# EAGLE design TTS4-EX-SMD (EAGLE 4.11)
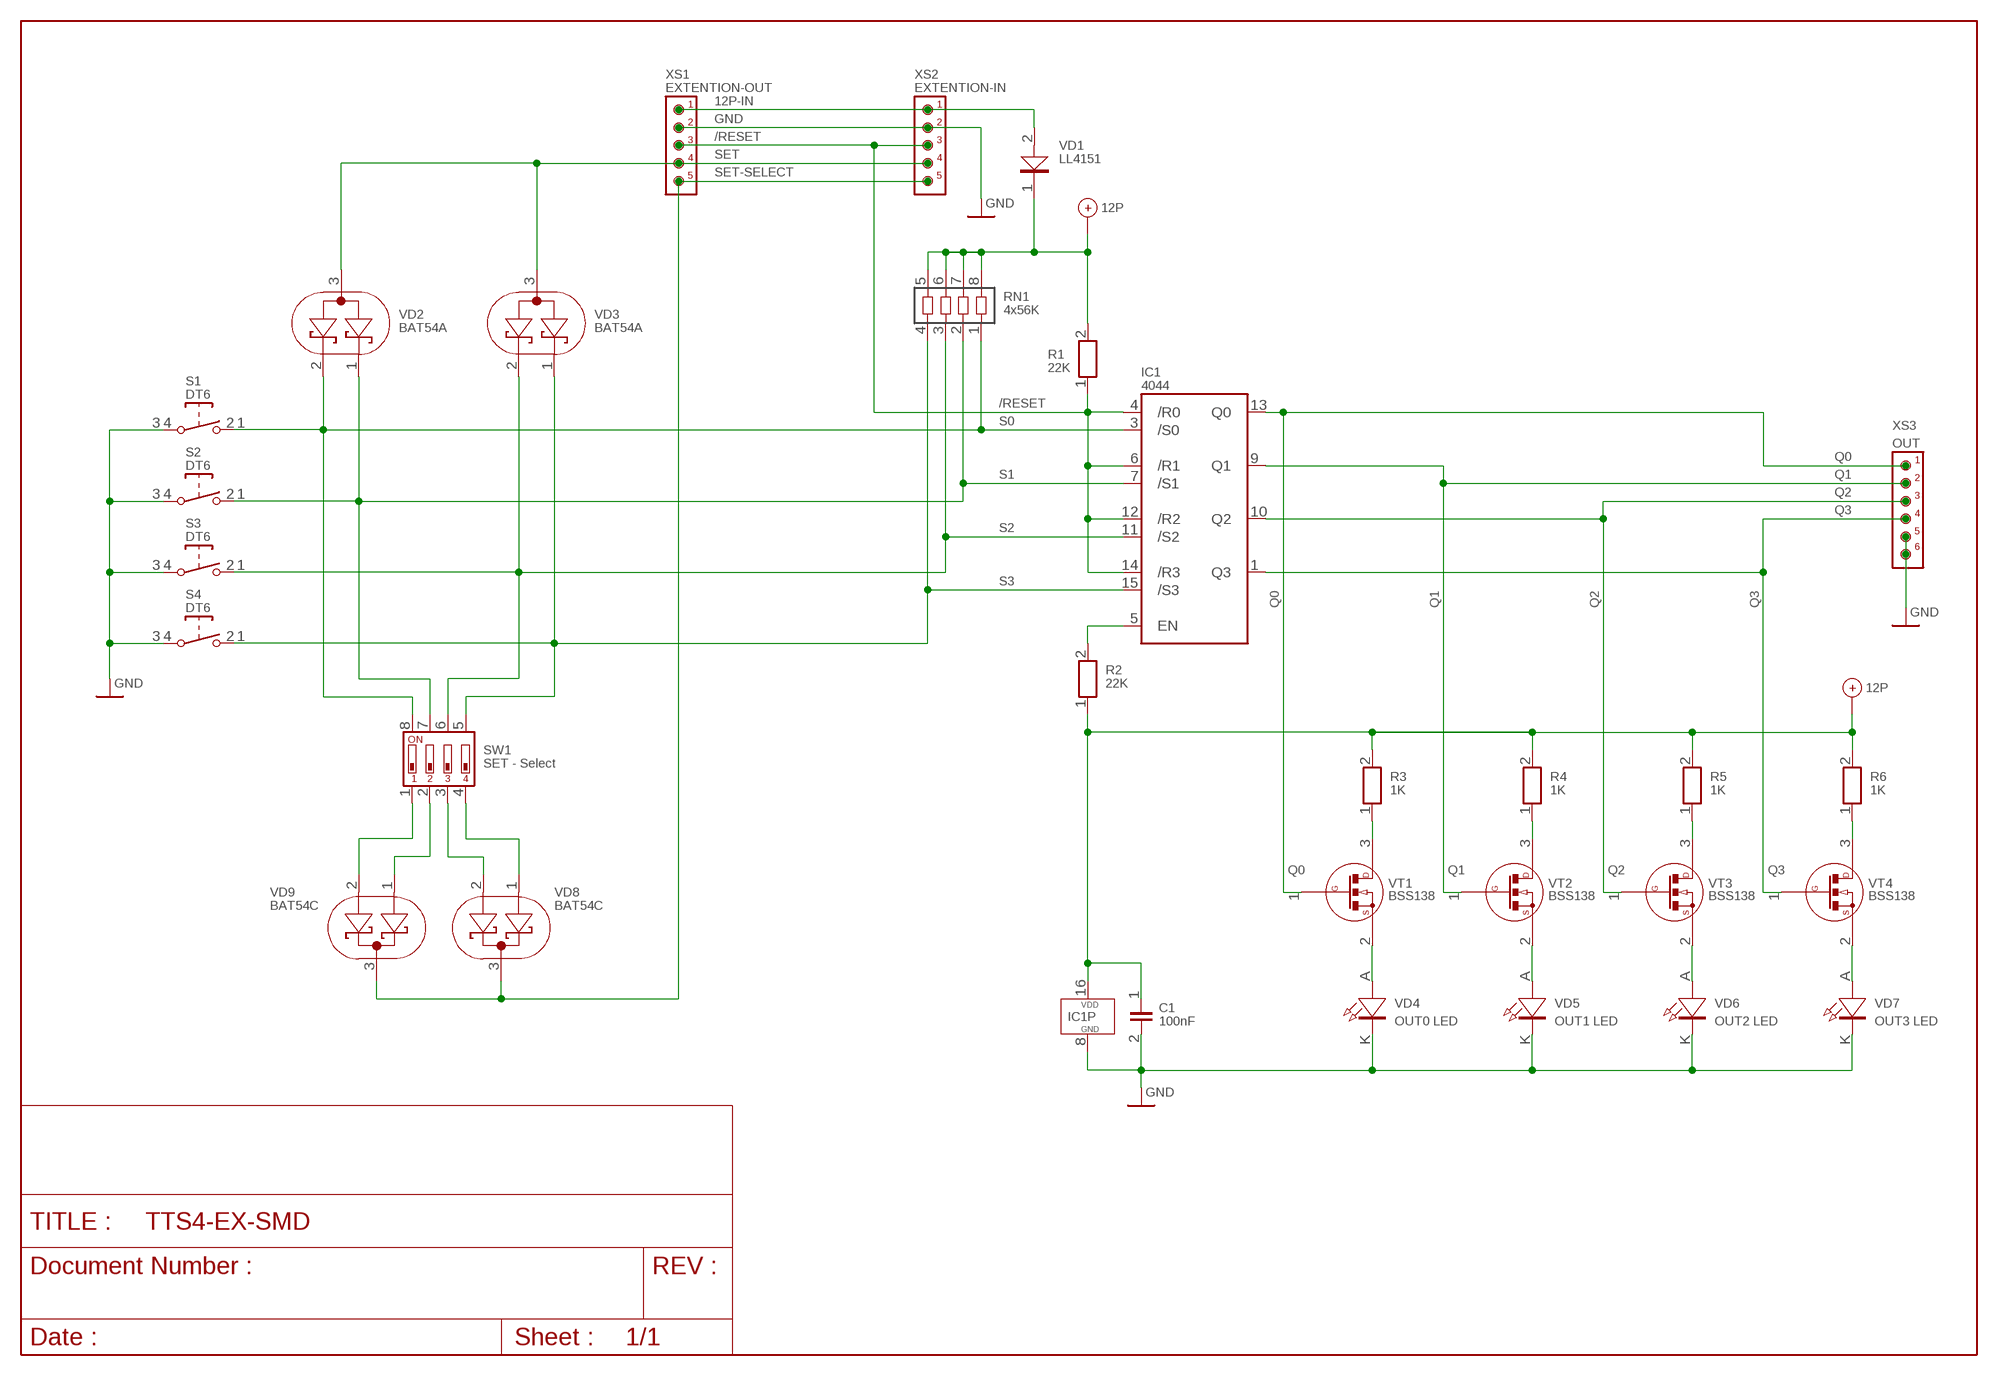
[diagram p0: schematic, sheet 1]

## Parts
C1  100nF  C-SMD_0603S  [0603S]
IC1  4044  4044_SO  [SO16]
R1  22K  R-SMD_0603S  [0603S]
R2  22K  R-SMD_0603S  [0603S]
R3  1K  R-SMD_1206S  [1206S]
R4  1K  R-SMD_1206S  [1206S]
R5  1K  R-SMD_1206S  [1206S]
R6  1K  R-SMD_1206S  [1206S]
RN1  4x56K  RNCAT16L  [RNCAT16]
S1  DT6  DT6-H  [DT6-HOLE]
S2  DT6  DT6-H  [DT6-HOLE]
S3  DT6  DT6-H  [DT6-HOLE]
S4  DT6  DT6-H  [DT6-HOLE]
SW1  SET - Select  SW_DIP-4SMS  [SMS4]
VD1  LL4151  LL4151_N  [MLL34]
VD2  BAT54A  BAT54AL  [SOT23L]
VD3  BAT54A  BAT54AL  [SOT23L]
VD4  OUT0 LED  LED3MM  [LED-3MM]
VD5  OUT1 LED  LED3MM  [LED-3MM]
VD6  OUT2 LED  LED3MM  [LED-3MM]
VD7  OUT3 LED  LED3MM  [LED-3MM]
VD8  BAT54C  BAT54C_L  [SOT23L]
VD9  BAT54C  BAT54C_L  [SOT23L]
VT1  BSS138  BSS138_L  [SOT23L]
VT2  BSS138  BSS138_L  [SOT23L]
VT3  BSS138  BSS138_L  [SOT23L]
VT4  BSS138  BSS138_L  [SOT23L]
XS1  EXTENTION-OUT  PF1X5  [1X5]
XS2  EXTENTION-IN  PF1X5  [1X5]
XS3  OUT  PF1X6  [1X6]

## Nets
12P: C1.1 IC1.16(VDD) R1.2 R2.1 R3.2 R4.2 R5.2 R6.2 RN1.5 RN1.6 RN1.7 RN1.8 VD1.1(K)
12P-IN: VD1.2(A) XS1.1 XS2.1
/RESET: IC1.4(/R0) IC1.6(/R1) IC1.12(/R2) IC1.14(/R3) R1.1 XS1.3 XS2.3
GND: C1.2 IC1.8(GND) S1.3(P) S1.4(P) S2.3(P) S2.4(P) S3.3(P) S3.4(P) S4.3(P) S4.4(P) VD4.K VD5.K VD6.K VD7.K XS1.2 XS2.2 XS3.5 XS3.6
N$5: VD4.A VT1.2(S)
N$6: VD5.A VT2.2(S)
N$7: VD6.A VT3.2(S)
N$8: VD7.A VT4.2(S)
N$9: IC1.5(EN) R2.2
N$11: R3.1 VT1.3(D)
N$12: R4.1 VT2.3(D)
N$13: R5.1 VT3.3(D)
N$14: R6.1 VT4.3(D)
Q0: IC1.13(Q0) VT1.1(G) XS3.1
Q1: IC1.9(Q1) VT2.1(G) XS3.2
Q2: IC1.10(Q2) VT3.1(G) XS3.3
Q3: IC1.1(Q3) VT4.1(G) XS3.4
S0: IC1.3(/S0) RN1.1 S1.1(S) S1.2(S) SW1.8 VD2.2(K2)
S1: IC1.7(/S1) RN1.2 S2.1(S) S2.2(S) SW1.7 VD2.1(K1)
S2: IC1.11(/S2) RN1.3 S3.1(S) S3.2(S) SW1.6 VD3.2(K2)
S3: IC1.15(/S3) RN1.4 S4.1(S) S4.2(S) SW1.5 VD3.1(K1)
SET: VD2.3(A) VD3.3(A) XS1.4 XS2.4
SET-SELECT: VD8.3(K) VD9.3(K) XS1.5 XS2.5
SL1: SW1.1 VD9.2(A2)
SL2: SW1.2 VD9.1(A1)
SL3: SW1.3 VD8.2(A2)
SL4: SW1.4 VD8.1(A1)

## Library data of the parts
C1 = RLC - SMD:C-SMD_: SMD - Kondensator
IC1 = 40XXSMD:4044_: vier RS - Flip - Flop mit Tristate - Ausgängen
R1-R6 = RLC - SMD:R-SMD_: SMD - Widerstände
RN1 = RLC - SMD:RNCAT16: SMD - Widerstandsnetz , 4 unabhängige Einzelwiderstände
S1-S4 = SWITCH:DT: ITT SWITCH
SW1 = DIL - SW:SW_DIP-4
VD1 = SMD:LL4151_
VD2 VD3 = DC:BAT54A
VD4-VD7 = OPTO:LED
VD8 VD9 = DC:BAT54C_: Doppelschottkydiode mit gemeinsamer Katode
VT1-VT4 = DC:BSS138_: N - Kanal MOSFET
XS1 XS2 = PF:PF1X5
XS3 = PF:PF1X6

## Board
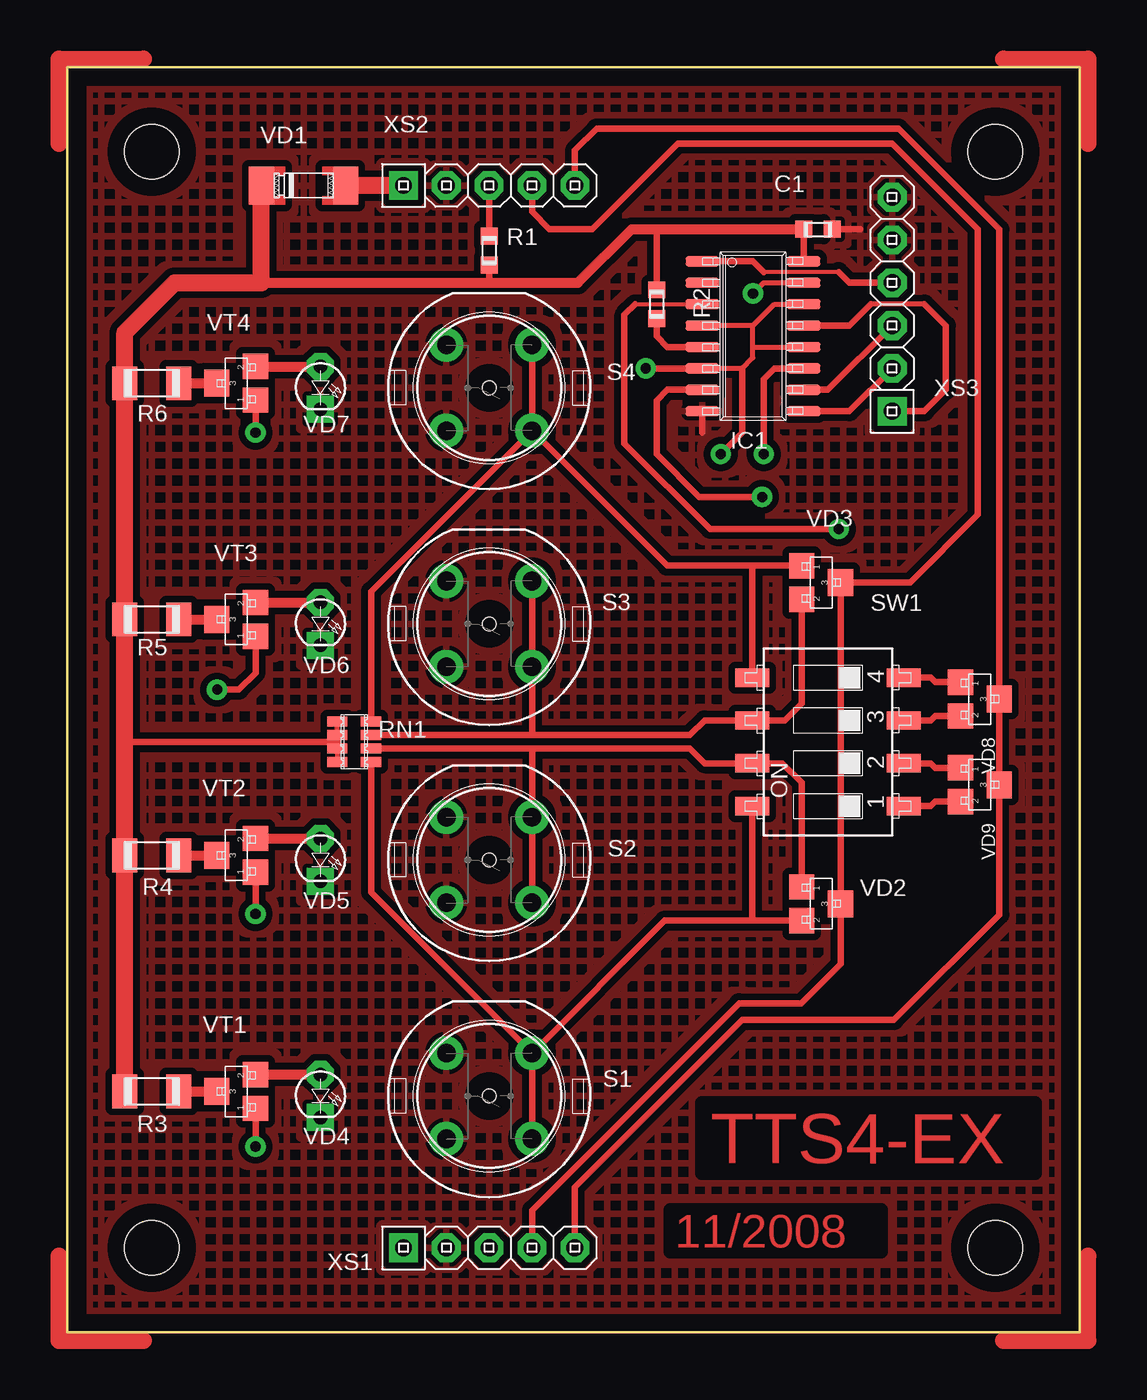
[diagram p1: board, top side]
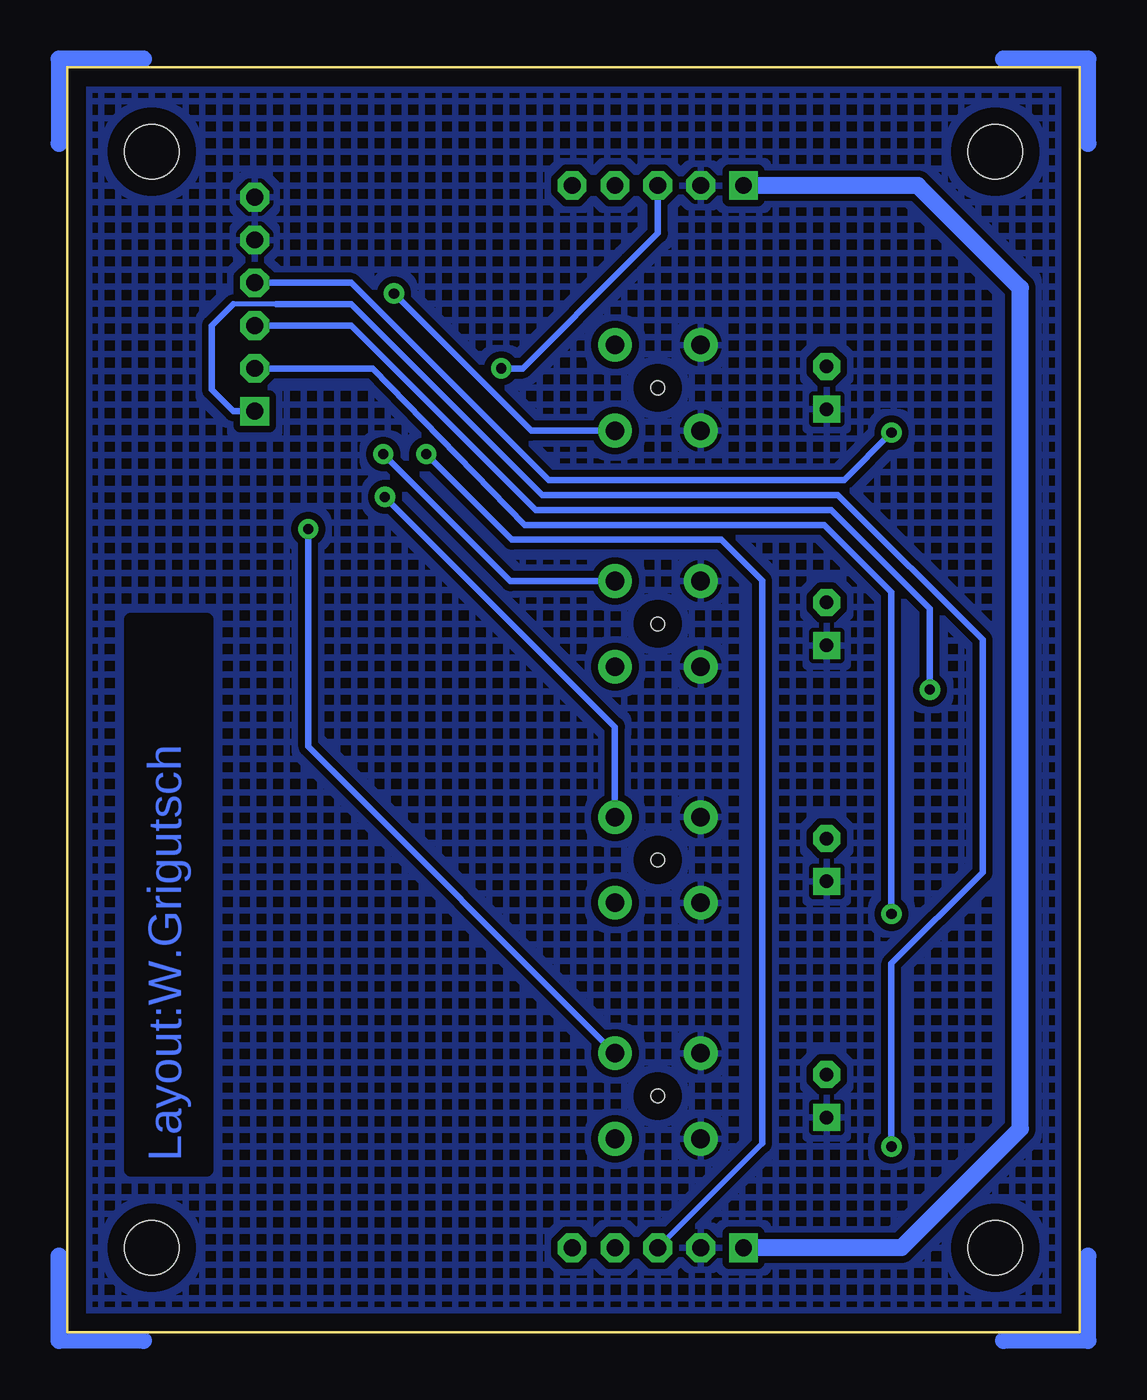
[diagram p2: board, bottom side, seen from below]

Size 60 x 75 mm. Coordinates in mm from the lower left corner, seen from the top.
Outline: 0,0 60,0 60,75 0,75 0,0
Copper layers (1*16): Top 0.035mm / dielectric 1.5mm / Bottom 0.035mm
Design rules "default": minimum track width 6mil, minimum drill 20mil, track to track 6mil, track to pad 6mil, pad to pad 6mil, via to via 10mil, smd to smd 0mil, copper to edge 40mil, drill to drill 8mil, minimum pad ring 10mil, minimum via ring 8mil, stop-mask expansion 4mil, vias tented up to drill 0mil, thermal gap 10mil
Holes 3.2 mm at 5,5 55,5 5,70 55,70
tRestrict: area 37.6,9.4 to 57.4,13.6; area 35.8,4.8 to 48.2,7.2
bRestrict: area 51.8,9.6 to 56.2,42.2

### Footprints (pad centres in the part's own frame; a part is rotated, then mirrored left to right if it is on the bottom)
0603S = smd 1 x 1: 1 -0.85,0; 2 0.85,0
SO16 = smd 0.61 x 2: 1 -4.445,-3; 2 -3.175,-3; 3 -1.905,-3; 4 -0.635,-3; 5 0.635,-3; 6 1.905,-3; 7 3.175,-3; 8 4.445,-3; 9 4.445,3; 10 3.175,3; 11 1.905,3; 12 0.635,3; 13 -0.635,3; 14 -1.905,3; 15 -3.175,3; 16 -4.445,3
1206S = smd 1.5 x 2: 1 -1.6,0; 2 1.6,0
RNCAT16 = smd 0.6 x 1.2: 1 -1.2,-1; 2 -0.4,-1; 3 0.4,-1; 4 1.2,-1; 5 1.2,1; 6 0.4,1; 7 -0.4,1; 8 -1.2,1
DT6-HOLE = drill 1.1 pad 2 round: 1 -2.54,2.54; 2 2.54,2.54; 3 2.54,-2.54; 4 -2.54,-2.54 | hole 0.8: 0,0
SMS4 = smd 1.092 x 2.007: 1 -3.81,-4.496; 2 -1.27,-4.496; 3 1.27,-4.496; 4 3.81,-4.496; 5 3.81,4.496; 6 1.27,4.496; 7 -1.27,4.496; 8 -3.81,4.496
MLL34 = smd 1.5 x 2.25: 1 -2.5,0; 2 2.5,0
SOT23L = smd 1.5 x 1.5: 1 -1,-1.15; 2 1,-1.15 | smd 1.6 x 1.5: 3 0,1.15
LED-3MM = drill 0.8 pad 1.6 octagon: A 1.27,0 | drill 0.8 pad 1.6 square: K -1.27,0
1X5 = drill 1 pad 1.7 square: 1 -5.08,0 | drill 1 pad 1.7 octagon: 2 -2.54,0; 3 0,0; 4 2.54,0; 5 5.08,0
1X6 = drill 1 pad 1.7 square: 1 -6.35,0 | drill 1 pad 1.7 octagon: 2 -3.81,0; 3 -1.27,0; 4 1.27,0; 5 3.81,0; 6 6.35,0

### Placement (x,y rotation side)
C1  44.49,65.41 0 top
IC1  40.64,59.05 270 top
R1  25,64.14 270 top
R2  34.92,60.96 270 top
R3  5,14.27 180 top
R4  5,28.27 180 top
R5  5,42.27 180 top
R6  5,56.27 180 top
RN1  17,35 90 top
S1  25,14 270 top
S2  25,28 270 top
S3  25,42 270 top
S4  25,56 270 top
SW1  45.09,35 90 top
VD1  14,68 0 top
VD2  44.69,25.4 270 top
VD3  44.69,44.45 270 top
VD4  15,14 90 top
VD5  15,28 90 top
VD6  15,42 90 top
VD7  15,56 90 top
VD8  54.09,37.54 270 top
VD9  54.09,32.46 270 top
VT1  10,14.27 90 top
VT2  10,28.27 90 top
VT3  10,42.27 90 top
VT4  10,56.27 90 top
XS1  25,5 0 top
XS2  25,68 0 top
XS3  48.9,60.96 90 top

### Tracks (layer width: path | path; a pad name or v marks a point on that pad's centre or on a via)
12P
  Top 0.3: RN1.6 RN1.5 | RN1.7 RN1.8
  Top 0.4: 16,35 RN1.6 | 16,35 RN1.7 | 3.4,35 16,35 | C1.1 IC1.16 | 25,62.23 R1.2 | 34.92,65.41 R2.1
  Top 0.6: 11.5,62.23 25,62.23 30.27,62.23 33.44,65.41 34.92,65.41 C1.1
  Top 1: R3.2 R4.2 3.4,35 R5.2 R6.2 3.4,59.28 6.35,62.23 11.5,62.23 VD1.1
12P-IN
  Top 1: XS2.1 VD1.2
  Bottom 1: XS2.1 9.58,68 3.5,61.92 3.5,12.06 10.56,5 XS1.1
/RESET  (via drill 0.6 pad 1.2)
  Top 0.3: 40.64,59.69 IC1.4 | IC1.14 41.91,60.96 40.64,59.69 | IC1.6 40.01,57.15 40.64,57.78 40.64,58.42 | 40.64,58.42 IC1.12 | 40.64,58.42 40.64,59.69
  Top 0.4: v38.73,52.07 40.01,53.34 40.01,57.15 | XS2.3 R1.1 | IC1.6 v34.29,57.15
  Bottom 0.3: XS1.3 18.82,11.19
  Bottom 0.4: v38.73,52.07 33.66,46.99 21.24,46.99 18.82,44.56 18.82,11.19 | XS2.3 25,65.17 26.67,63.5 33.02,57.15 v34.29,57.15
GND
  Top 0.4: C1.2 46.99,65.41 | IC1.8 37.64,53.34
  pour Top (isolate 0.4, hatched): 1,1 1,74 59,74 59,1
  pour Bottom (isolate 0.4, hatched): 1,1 1,74 59,74 59,1
N$1
  Top 1: 4.5,-0.5 -0.5,-0.5 -0.5,4.5
N$2
  Top 1: 55.5,-0.5 60.5,-0.5 60.5,4.5
N$3
  Top 1: 4.5,75.5 -0.5,75.5 -0.5,70.5
N$4
  Top 1: 60.5,70.5 60.5,75.5 55.5,75.5
N$5
  Top 0.6: VT1.2 VD4.A
N$6
  Top 0.6: VT2.2 VD5.A
N$7
  Top 0.6: VT3.2 VD6.A
N$8
  Top 0.6: VT4.2 VD7.A
N$9
  Top 0.4: R2.2 34.92,59.05 35.56,58.42 IC1.5
N$10
  Bottom 1: 4.5,-0.5 -0.5,-0.5 -0.5,4.5
N$11
  Top 0.6: R3.1 VT1.3
N$12
  Top 0.6: R4.1 VT2.3
N$13
  Top 0.6: R5.1 VT3.3
N$14
  Top 0.6: R6.1 VT4.3
N$15
  Bottom 1: 55.5,-0.5 60.5,-0.5 60.5,4.5
N$16
  Bottom 1: 4.5,75.5 -0.5,75.5 -0.5,70.5
N$17
  Bottom 1: 60.5,70.5 60.5,75.5 55.5,75.5
Q0  (via drill 0.6 pad 1.2)
  Top 0.3: 50.8,60.96 47.62,60.96
  Top 0.4: v11.15,11 VT1.1 | IC1.13 46.35,59.69 47.62,60.96 | 50.8,60.96 52.07,59.69 52.07,55.88 50.8,54.61 XS3.1
  Bottom 0.3: 47.62,60.96 50.16,60.96
  Bottom 0.4: v11.15,11 11.15,21.85 5.75,27.25 5.75,41.06 14.34,49.65 31.86,49.65 43.18,60.96 47.62,60.96 | XS3.1 50.16,54.61 51.44,55.88 51.44,59.69 50.16,60.96
Q1  (via drill 0.6 pad 1.2)
  Top 0.4: v11.15,24.8 VT2.1 | IC1.9 46.35,54.61 XS3.2
  Bottom 0.4: v11.15,24.8 11.15,43.9 15.12,47.88 32.88,47.88 41.91,57.15 XS3.2
Q2  (via drill 0.6 pad 1.2)
  Top 0.4: VT3.1 11.15,39.09 10.16,38.1 v8.87,38.1 | IC1.10 45.09,55.88 XS3.3
  Bottom 0.4: v8.87,38.1 8.87,42.91 14.72,48.76 32.25,48.76 43.18,59.69 XS3.3
Q3  (via drill 0.6 pad 1.2)
  Top 0.25: 45.72,62.87 41.27,62.87
  Top 0.4: IC1.1 40.64,63.5 41.27,62.87 | 45.72,62.87 46.35,62.23 XS3.4 | v11.15,53.34 VT4.1
  Bottom 0.4: v11.15,53.34 13.96,50.53 31.48,50.53 43.18,62.23 XS3.4
S0  (via drill 0.6 pad 1.2)
  Top 0.25: 33.66,60.96 IC1.3
  Top 0.4: S1.2 S1.1 | S1.1 18,26.08 RN1.1 | 40.59,24.4 SW1.8 | 40.59,24.4 VD2.2 | 33.66,60.96 33.02,60.33 33.02,52.7 38.1,47.62 v45.72,47.62 | 40.59,24.4 35.4,24.4 S1.1
  Bottom 0.4: S1.1 45.72,34.72 v45.72,47.62
S1  (via drill 0.6 pad 1.2)
  Top 0.4: S2.2 S2.1 27.54,34.6 | RN1.2 27.54,34.6 | 27.54,34.6 36.9,34.6 37.77,33.73 SW1.7 42.39,33.73 43.53,32.58 VD2.1 | IC1.7 35.56,55.88 34.92,55.24 34.92,52.07 37.47,49.53 v41.18,49.53
  Bottom 0.4: S2.1 27.54,35.89 v41.18,49.53
S2  (via drill 0.6 pad 1.2)
  Top 0.4: S3.1 S3.2 27.54,35.4 | RN1.3 27.54,35.4 | 27.54,35.4 36.9,35.4 37.77,36.27 SW1.6 42.54,36.27 43.53,37.27 VD3.2 | IC1.11 41.91,57.15 41.27,56.52 v41.27,52.07
  Bottom 0.4: S3.1 33.74,44.54 v41.27,52.07
S3  (via drill 0.6 pad 1.2)
  Top 0.3: IC1.15 41.27,62.23 v40.64,61.59
  Top 0.4: S4.2 S4.1 | 40.59,45.45 SW1.5 | S4.2 18,43.92 RN1.4 | 40.59,45.45 VD3.1 | 40.59,45.45 35.55,45.45 S4.2
  Bottom 0.4: S4.2 32.51,53.46 v40.64,61.59
SET
  Top 0.4: XS2.4 27.54,66.44 28.57,65.41 31.11,65.41 36.2,70.48 48.9,70.48 53.98,65.41 53.98,48.48 49.95,44.45 VD3.3 VD2.3 45.84,21.84 43.5,19.5 39.82,19.5 27.54,7.22 XS1.4
SET-SELECT
  Top 0.4: XS2.5 30.08,70.08 31.36,71.37 49.28,71.37 55.24,65.41 VD8.3 VD9.3 55.24,24.75 49,18.5 40,18.5 30.08,8.58 XS1.5
SL1
  Top 0.4: SW1.1 51.17,31.19 51.45,31.46 VD9.2
SL2
  Top 0.4: SW1.2 51.17,33.73 51.45,33.46 VD9.1
SL3
  Top 0.4: SW1.3 51.17,36.27 51.45,36.54 VD8.2
SL4
  Top 0.4: SW1.4 51.17,38.81 51.45,38.54 VD8.1

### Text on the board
Top: TTS4-EX | 11/2008
Bottom: Layout:W.Grigutsch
